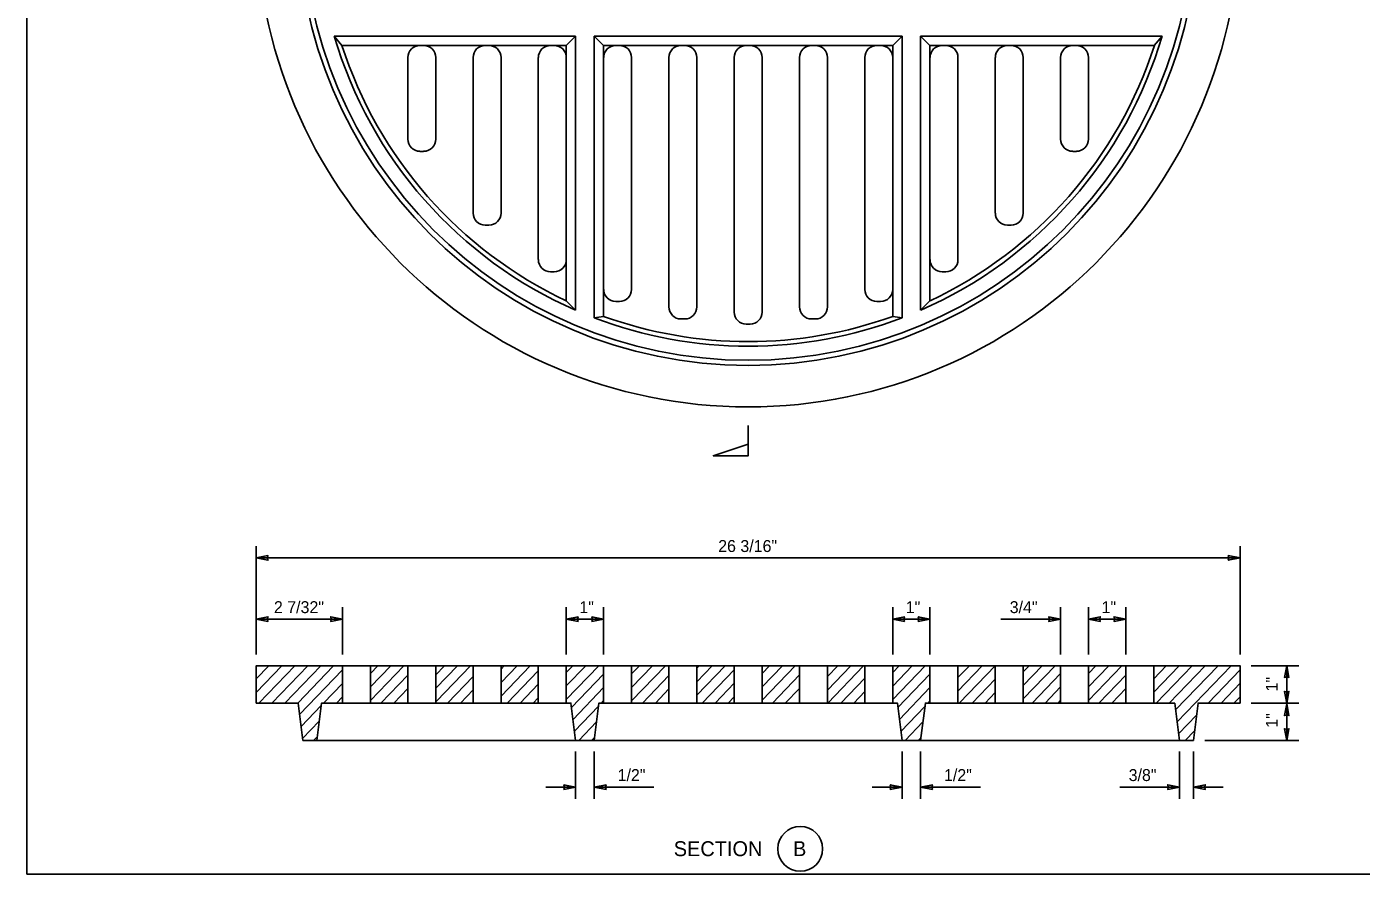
# Model space of a CAD drawing. Extents: x 99862 to 103151, y 100000 to 102076.
# Drawn here: x 99862 to 101651, y 100000 to 101135 of the extents above; entities that cross this region are included whole.
import ezdxf

# ---------------------------------------------------------------- set-up
doc = ezdxf.new("R2010")
doc.units = 0
for name, color, linetype in [('Level 1', 7, 'Continuous'), ('Level 12', 7, 'Continuous'), ('Level 15', 7, 'Continuous'), ('Level 18', 7, 'Continuous'), ('Level 20', 7, 'Continuous'), ('Level 60', 7, 'Continuous'), ('Level 9', 7, 'Continuous')]:
    doc.layers.add(name, color=color, linetype=linetype)

msp = doc.modelspace()

# ---------------------------------------------------------------- linework, layer by layer
at = {"layer": 'Level 1'}
msp.add_lwpolyline([(99862, 99999.5), (103151, 99999.5), (103151, 102075.5), (99862, 102075.5)], close=True, dxfattribs=at)
at = {"layer": 'Level 12'}
for p, q in [((100169.7, 100243.2), (100204, 100278.9)), ((100169.7, 100261.2), (100186.7, 100278.9)), ((100173.3, 100228.9), (100221.4, 100278.9)), ((100190.7, 100228.9), (100238.7, 100278.9)), ((100208, 100228.9), (100256.1, 100278.9)), ((100225.3, 100228.9), (100272.8, 100278.3)), ((100227.9, 100213.5), (100285.3, 100273.3)), ((100322.8, 100250.6), (100350.1, 100278.9)), ((100322.8, 100268.6), (100332.7, 100278.9)), ((100322.8, 100232.5), (100367.4, 100278.9)), ((100409.8, 100266.2), (100422.1, 100278.9)), ((100410.4, 100248.8), (100439.4, 100278.9)), ((100411.1, 100231.4), (100456.7, 100278.9)), ((100497.8, 100256.3), (100519.6, 100278.9)), ((100497.8, 100274.3), (100502.2, 100278.9)), ((100497.8, 100238.2), (100536.9, 100278.9)), ((100506.2, 100228.9), (100547.8, 100272.2)), ((100585.3, 100251.8), (100611.4, 100278.9)), ((100585.3, 100269.8), (100594.1, 100278.9)), ((100585.3, 100233.8), (100628.7, 100278.9)), ((100672.8, 100249.9), (100700.7, 100278.9)), ((100672.8, 100267.9), (100683.4, 100278.9)), ((100672.8, 100231.8), (100718.1, 100278.9)), ((100760.3, 100257.5), (100780.9, 100278.9)), ((100760.3, 100275.5), (100763.6, 100278.9)), ((100760.3, 100239.5), (100798.3, 100278.9)), ((100767.5, 100228.9), (100810.3, 100273.4)), ((100847.8, 100250.7), (100875, 100278.9)), ((100847.8, 100268.7), (100857.6, 100278.9)), ((100847.8, 100232.6), (100892.3, 100278.9)), ((100935.3, 100246.4), (100966.5, 100278.9)), ((100935.3, 100264.5), (100949.2, 100278.9)), ((100935.8, 100228.9), (100983.9, 100278.9)), ((101022.8, 100233.7), (101066.3, 100278.9)), ((101022.8, 100251.7), (101049, 100278.9)), ((101022.8, 100269.7), (101031.6, 100278.9)), ((101110.3, 100245), (101142.9, 100278.9)), ((101110.3, 100263), (101125.6, 100278.9)), ((101112.4, 100229.2), (101160.3, 100279)), ((101197.8, 100252.6), (101223.1, 100278.9)), ((101197.8, 100270.7), (101205.8, 100278.9)), ((101197.8, 100234.6), (101240.4, 100278.9)), ((101285.3, 100250.5), (101312.7, 100278.9)), ((101285.3, 100268.5), (101295.3, 100278.9)), ((101285.3, 100232.4), (101330, 100278.9)), ((101372.8, 100243.4), (101407, 100278.9)), ((101372.8, 100261.4), (101389.6, 100278.9)), ((101376.2, 100228.9), (101424.3, 100278.9)), ((101393.6, 100228.9), (101441.6, 100278.9)), ((101402.1, 100219.7), (101459, 100278.9)), ((101404.1, 100203.8), (101476.3, 100278.9)), ((101445.6, 100228.9), (101488.5, 100273.5)), ((100260, 100228.9), (100285.3, 100255.2)), ((100336.7, 100228.9), (100372.8, 100266.5)), ((100426, 100228.9), (100460.3, 100264.6)), ((100523.5, 100228.9), (100547.8, 100254.2)), ((100592.3, 100223), (100635.3, 100267.7)), ((100687.4, 100228.9), (100722.8, 100265.8)), ((100784.9, 100228.9), (100810.3, 100255.4)), ((100861.6, 100228.9), (100897.8, 100266.6)), ((100953.2, 100228.9), (100985.3, 100262.4)), ((101029.8, 100222.9), (101072.8, 100267.6)), ((101129.5, 100228.9), (101160.3, 100260.9)), ((101209.7, 100228.9), (101247.8, 100268.6)), ((101299.3, 100228.9), (101335.3, 100266.4)), ((101462.9, 100228.9), (101488.5, 100255.4)), ((100277.4, 100228.9), (100285.3, 100237.2)), ((100354, 100228.9), (100372.8, 100248.5)), ((100443.4, 100228.9), (100460.3, 100246.6)), ((100540.9, 100228.9), (100547.8, 100236.1)), ((100594.3, 100207), (100635.3, 100249.7)), ((100704.7, 100228.9), (100722.8, 100247.8)), ((100802.2, 100228.9), (100810.3, 100237.4)), ((100878.9, 100228.9), (100897.8, 100248.6)), ((100970.5, 100228.9), (100985.3, 100244.3)), ((101031.8, 100207), (101072.8, 100249.6)), ((101146.9, 100228.9), (101160.3, 100242.9)), ((101227, 100228.9), (101247.8, 100250.5)), ((101316.6, 100228.9), (101335.3, 100248.4)), ((101480.3, 100228.9), (101488.5, 100237.4)), ((100229.9, 100197.6), (100256.8, 100225.5)), ((100596.3, 100191.1), (100628.6, 100224.6)), ((100632.7, 100228.9), (100635.3, 100231.7)), ((101033.8, 100191), (101066, 100224.5)), ((101070.3, 100228.9), (101072.8, 100231.6)), ((101244.4, 100228.9), (101247.8, 100232.5)), ((100231.9, 100181.6), (100254.2, 100204.8)), ((100602, 100178.9), (100626, 100203.9)), ((101039.5, 100178.9), (101063.4, 100203.8)), ((101406.1, 100187.8), (101429.9, 100212.6)), ((100246.6, 100178.9), (100251.6, 100184.1)), ((100619.3, 100178.9), (100623.4, 100183.1)), ((101056.9, 100178.9), (101060.9, 100183)), ((101414.9, 100178.9), (101427.3, 100191.9))]:
    msp.add_line(p, q, dxfattribs=at)
at = {"layer": 'Level 15'}
for p, q in [((100169.7, 100439.3), (100169.7, 100293.9)), ((101488.5, 100439.3), (101488.5, 100293.9)), ((101488.5, 100423.3), (100169.7, 100423.3)), ((100285.3, 100293.9), (100285.3, 100357.4)), ((100585.3, 100293.9), (100585.3, 100357.4)), ((100635.3, 100293.9), (100635.3, 100357.4)), ((101022.8, 100293.9), (101022.8, 100357.4)), ((101072.8, 100293.9), (101072.8, 100357.4)), ((101247.8, 100293.9), (101247.8, 100357.4)), ((101285.3, 100293.9), (101285.3, 100357.4)), ((101335.3, 100293.9), (101335.3, 100357.4)), ((100285.3, 100341.4), (100169.7, 100341.4)), ((100585.3, 100341.4), (100635.3, 100341.4)), ((101022.8, 100341.4), (101072.8, 100341.4)), ((101167.8, 100341.4), (101247.8, 100341.4)), ((101285.3, 100341.4), (101335.3, 100341.4)), ((101567, 100278.9), (101503.5, 100278.9)), ((101551, 100278.9), (101551, 100228.9)), ((101567, 100228.9), (101503.5, 100228.9)), ((101551, 100227.9), (101551, 100178.9)), ((100597.8, 100163.9), (100597.8, 100100.4)), ((100622.8, 100163.9), (100622.8, 100100.4)), ((101035.3, 100163.9), (101035.3, 100100.4)), ((101060.3, 100163.9), (101060.3, 100100.4)), ((101407.2, 100163.9), (101407.2, 100100.4)), ((101426, 100163.9), (101426, 100100.4)), ((101567, 100178.9), (101441, 100178.9)), ((100597.8, 100116.4), (100557.8, 100116.4)), ((100702.8, 100116.4), (100622.8, 100116.4)), ((101035.3, 100116.4), (100995.3, 100116.4)), ((101140.3, 100116.4), (101060.3, 100116.4)), ((101327.2, 100116.4), (101407.2, 100116.4)), ((101426, 100116.4), (101466, 100116.4))]:
    msp.add_line(p, q, dxfattribs=at)
for points in [[(100169.7, 100423.3), (100185.4, 100420.2), (100184.7, 100423.3), (100185.4, 100426.4)], [(101488.5, 100423.3), (101472.7, 100420.2), (101473.5, 100423.3), (101472.7, 100426.4)], [(100169.7, 100341.4), (100185.4, 100338.3), (100184.7, 100341.4), (100185.4, 100344.5)], [(100285.3, 100341.4), (100269.6, 100338.3), (100270.3, 100341.4), (100269.6, 100344.5)], [(100585.3, 100341.4), (100601.1, 100338.3), (100600.3, 100341.4), (100601.1, 100344.5)], [(100635.3, 100341.4), (100619.6, 100338.3), (100620.3, 100341.4), (100619.6, 100344.5)], [(101022.8, 100341.4), (101038.6, 100338.3), (101037.8, 100341.4), (101038.6, 100344.5)], [(101072.8, 100341.4), (101057.1, 100338.3), (101057.8, 100341.4), (101057.1, 100344.5)], [(101247.8, 100341.4), (101232.1, 100338.3), (101232.8, 100341.4), (101232.1, 100344.5)], [(101285.3, 100341.4), (101301.1, 100338.3), (101300.3, 100341.4), (101301.1, 100344.5)], [(101335.3, 100341.4), (101319.6, 100338.3), (101320.3, 100341.4), (101319.6, 100344.5)], [(101551, 100278.9), (101547.9, 100263.2), (101551, 100263.9), (101554, 100263.2)], [(101551, 100228.9), (101547.9, 100244.6), (101551, 100243.9), (101554, 100244.6)], [(101551, 100227.9), (101547.9, 100212.1), (101551, 100212.9), (101554, 100212.1)], [(101551, 100178.9), (101547.9, 100194.6), (101551, 100193.9), (101554, 100194.6)], [(100597.8, 100116.4), (100582.1, 100113.3), (100582.8, 100116.4), (100582.1, 100119.5)], [(100622.8, 100116.4), (100638.6, 100113.3), (100637.8, 100116.4), (100638.6, 100119.5)], [(101035.3, 100116.4), (101019.6, 100113.3), (101020.3, 100116.4), (101019.6, 100119.5)], [(101060.3, 100116.4), (101076.1, 100113.3), (101075.3, 100116.4), (101076.1, 100119.5)], [(101407.2, 100116.4), (101391.5, 100113.3), (101392.2, 100116.4), (101391.5, 100119.5)], [(101426, 100116.4), (101441.7, 100113.3), (101441, 100116.4), (101441.7, 100119.5)]]:
    msp.add_lwpolyline(points, close=True, dxfattribs=at)
at = {"layer": 'Level 18'}
for p, q in [((100274.3, 101122.6), (100597.8, 101122.6)), ((100284.6, 101110.1), (100274.3, 101122.6)), ((100585.3, 101110.1), (100597.8, 101122.6)), ((100597.8, 100755.2), (100597.8, 101122.6)), ((100622.8, 100745), (100622.8, 101122.6)), ((100635.3, 101110.1), (100622.8, 101122.6)), ((100622.8, 101122.6), (101035.3, 101122.6)), ((101022.8, 101110.1), (101035.3, 101122.6)), ((101035.3, 100745), (101035.3, 101122.6)), ((101060.3, 100755.2), (101060.3, 101122.6)), ((101060.3, 101122.6), (101383.9, 101122.6)), ((101060.3, 101122.6), (101072.8, 101110.1)), ((101373.5, 101110.1), (101383.9, 101122.6)), ((100284.6, 101110.1), (100585.3, 101110.1)), ((100389.1, 101110.1), (100394.1, 101110.1)), ((100476.6, 101110.1), (100481.6, 101110.1)), ((100564.1, 101110.1), (100569.1, 101110.1)), ((100585.3, 100767.8), (100585.3, 101110.1)), ((100635.3, 100747), (100635.3, 101110.1)), ((100635.3, 101110.1), (101022.8, 101110.1)), ((100651.6, 101110.1), (100656.6, 101110.1)), ((100739.1, 101110.1), (100744.1, 101110.1)), ((100826.6, 101110.1), (100831.6, 101110.1)), ((100914.1, 101110.1), (100919.1, 101110.1)), ((101001.6, 101110.1), (101006.6, 101110.1)), ((101022.8, 100747), (101022.8, 101110.1)), ((101072.8, 101110.1), (101373.5, 101110.1)), ((101072.8, 100767.8), (101072.8, 101110.1)), ((101089.1, 101110.1), (101094.1, 101110.1)), ((101176.6, 101110.1), (101181.6, 101110.1)), ((101264.1, 101110.1), (101269.1, 101110.1)), ((100372.8, 100984.4), (100372.8, 101093.8)), ((100410.3, 100984.4), (100410.3, 101093.8)), ((100460.3, 100885.4), (100460.3, 101093.8)), ((100497.8, 100885.4), (100497.8, 101093.8)), ((100547.8, 100823), (100547.8, 101093.8)), ((100585.3, 100823), (100585.3, 101093.8)), ((100635.3, 100783.2), (100635.3, 101093.8)), ((100672.8, 100783.2), (100672.8, 101093.8)), ((100722.8, 100759.7), (100722.8, 101093.8)), ((100760.3, 100759.7), (100760.3, 101093.8)), ((100810.3, 100752.8), (100810.3, 101093.8)), ((100847.8, 100752.8), (100847.8, 101093.8)), ((100897.8, 100759.7), (100897.8, 101093.8)), ((100935.3, 100759.7), (100935.3, 101093.8)), ((100985.3, 100783.2), (100985.3, 101093.8)), ((101022.8, 100783.2), (101022.8, 101093.8)), ((101072.8, 100823), (101072.8, 101093.8)), ((101110.3, 100823), (101110.3, 101093.8)), ((101160.3, 100885.4), (101160.3, 101093.8)), ((101197.8, 100885.4), (101197.8, 101093.8)), ((101247.8, 100984.4), (101247.8, 101093.8)), ((101285.3, 100984.4), (101285.3, 101093.8)), ((100389.1, 100968.1), (100394.1, 100968.1)), ((101269.1, 100968.1), (101264.1, 100968.1)), ((100476.6, 100869.1), (100481.6, 100869.1)), ((101181.6, 100869.1), (101176.6, 100869.1)), ((100564.1, 100806.7), (100569.1, 100806.7)), ((101094.1, 100806.7), (101089.1, 100806.7)), ((100585.3, 100767.8), (100597.8, 100755.2)), ((100651.6, 100766.9), (100656.6, 100766.9)), ((101006.6, 100766.9), (101001.6, 100766.9)), ((101072.8, 100767.8), (101060.3, 100755.2)), ((100635.3, 100747), (100622.8, 100745)), ((100739.1, 100743.5), (100744.1, 100743.5)), ((100826.6, 100736.6), (100831.6, 100736.6)), ((100919.1, 100743.5), (100914.1, 100743.5)), ((101022.8, 100747), (101035.3, 100745)), ((100285.3, 100278.9), (101372.8, 100278.9)), ((100285.3, 100228.9), (100585.3, 100228.9)), ((100635.3, 100228.9), (101022.8, 100228.9)), ((101072.8, 100228.9), (101372.8, 100228.9)), ((100251, 100178.9), (101407.2, 100178.9))]:
    msp.add_line(p, q, dxfattribs=at)
for points in [[(100285.3, 100228.9), (100285.3, 100278.9), (100169.7, 100278.9), (100169.7, 100228.9), (100226, 100228.9), (100232.2, 100178.9), (100251, 100178.9), (100257.2, 100228.9), (100285.3, 100228.9)], [(100372.8, 100228.9), (100372.8, 100278.9), (100322.8, 100278.9), (100322.8, 100228.9), (100372.8, 100228.9)], [(100460.3, 100228.9), (100460.3, 100278.9), (100410.3, 100278.9), (100410.3, 100228.9), (100460.3, 100228.9)], [(100547.8, 100228.9), (100547.8, 100278.9), (100497.8, 100278.9), (100497.8, 100228.9), (100547.8, 100228.9)], [(100635.3, 100228.9), (100635.3, 100278.9), (100585.3, 100278.9), (100585.3, 100228.9), (100591.6, 100228.9), (100597.8, 100178.9), (100622.8, 100178.9), (100629.1, 100228.9), (100635.3, 100228.9)], [(100694.9, 100278.9), (100672.8, 100278.9), (100672.8, 100228.9), (100722.8, 100228.9), (100722.8, 100278.9), (100694.9, 100278.9)], [(100810.3, 100228.9), (100810.3, 100278.9), (100760.3, 100278.9), (100760.3, 100228.9), (100810.3, 100228.9)], [(100872.2, 100278.9), (100847.8, 100278.9), (100847.8, 100228.9), (100897.8, 100228.9), (100897.8, 100278.9), (100872.2, 100278.9)], [(100985.3, 100228.9), (100985.3, 100278.9), (100935.3, 100278.9), (100935.3, 100228.9), (100985.3, 100228.9)], [(101072.8, 100228.9), (101072.8, 100278.9), (101022.8, 100278.9), (101022.8, 100228.9), (101029.1, 100228.9), (101035.3, 100178.9), (101060.3, 100178.9), (101066.6, 100228.9), (101072.8, 100228.9)], [(101160.3, 100228.9), (101160.3, 100278.9), (101110.3, 100278.9), (101110.3, 100228.9), (101160.3, 100228.9)], [(101247.8, 100228.9), (101247.8, 100278.9), (101197.8, 100278.9), (101197.8, 100228.9), (101247.8, 100228.9)], [(101335.3, 100228.9), (101335.3, 100278.9), (101285.3, 100278.9), (101285.3, 100228.9), (101335.3, 100228.9)], [(101401, 100228.9), (101407.2, 100178.9), (101426, 100178.9), (101432.2, 100228.9), (101488.5, 100228.9), (101488.5, 100278.9), (101372.8, 100278.9), (101372.8, 100228.9), (101401, 100228.9)]]:
    msp.add_lwpolyline(points, dxfattribs=at)
for radius in [659.4, 603.8, 596.9]:
    msp.add_circle((100829.1, 101285.1), radius, dxfattribs=at)
for centre, radius, start, end in [((100829.1, 101285.1), 578.1, 196.3247, 246.4218), ((100829.1, 101285.1), 578.1, 293.5782, 343.6753), ((100829.1, 101285.1), 571.9, 197.819, 244.7715), ((100389.1, 101093.8), 16.2, 90, 180), ((100394.1, 101093.8), 16.2, 0, 90), ((100476.6, 101093.8), 16.2, 90, 180), ((100481.6, 101093.8), 16.2, 0, 90), ((100564.1, 101093.8), 16.2, 90, 180), ((100569.1, 101093.8), 16.2, 0, 90), ((100651.6, 101093.8), 16.2, 90, 180), ((100656.6, 101093.8), 16.2, 0, 90), ((100739.1, 101093.8), 16.2, 90, 180), ((100744.1, 101093.8), 16.2, 0, 90), ((100826.6, 101093.8), 16.2, 90, 180), ((100831.6, 101093.8), 16.2, 0, 90), ((100914.1, 101093.8), 16.2, 90, 180), ((100919.1, 101093.8), 16.2, 0, 90), ((101001.6, 101093.8), 16.2, 90, 180), ((101006.6, 101093.8), 16.2, 0, 90), ((101089.1, 101093.8), 16.2, 90, 180), ((100829.1, 101285.1), 571.9, 295.2285, 342.181), ((101094.1, 101093.8), 16.2, 0, 90), ((101176.6, 101093.8), 16.2, 90, 180), ((101181.6, 101093.8), 16.2, 0, 90), ((101264.1, 101093.8), 16.2, 90, 180), ((101269.1, 101093.8), 16.2, 0, 90), ((100389.1, 100984.4), 16.2, 180, 270), ((100394.1, 100984.4), 16.2, 270, 0), ((101264.1, 100984.4), 16.2, 180, 270), ((101269.1, 100984.4), 16.2, 270, 0), ((100476.6, 100885.4), 16.2, 180, 270), ((100481.6, 100885.4), 16.2, 270, 0), ((101176.6, 100885.4), 16.2, 180, 270), ((101181.6, 100885.4), 16.2, 270, 0), ((100564.1, 100823), 16.2, 180, 270), ((100569.1, 100823), 16.2, 270, 0), ((101089.1, 100823), 16.2, 180, 270), ((101094.1, 100823), 16.2, 270, 0), ((100651.6, 100783.2), 16.2, 180, 270), ((100656.6, 100783.2), 16.2, 270, 0), ((101001.6, 100783.2), 16.2, 180, 270), ((101006.6, 100783.2), 16.2, 270, 0), ((100739.1, 100759.7), 16.2, 180, 270), ((100744.1, 100759.7), 16.2, 270, 0), ((100914.1, 100759.7), 16.2, 180, 270), ((100919.1, 100759.7), 16.2, 270, 0), ((100829.1, 101285.1), 578.1, 249.0988, 290.9012), ((100829.1, 101285.1), 571.9, 250.1964, 289.8036), ((100826.6, 100752.8), 16.2, 180, 270), ((100831.6, 100752.8), 16.2, 270, 0.0005)]:
    msp.add_arc(centre, radius, start, end, dxfattribs=at)
at = {"layer": 'Level 60'}
msp.add_line((99862, 99999.5), (99862, 99999.5), dxfattribs=at)
at = {"layer": 'Level 9'}
msp.add_line((100829.1, 100600.7), (100829.1, 100560.2), dxfattribs=at)
msp.add_lwpolyline([(100829.1, 100575.7), (100782.2, 100560.2), (100829.1, 100560.2)], close=True, dxfattribs=at)
msp.add_circle((100898.9, 100033.6), 30, dxfattribs=at)

# ---------------------------------------------------------------- texts
at = {"layer": 'Level 20'}
for s, rotation, p in [('26 3/16"', 0, (100788.9, 100431.3)), ('2 7/32"', 0, (100193.4, 100349.4)), ('1"', 0, (100602.8, 100349.4)), ('1"', 0, (101040.3, 100349.4)), ('3/4"', 360, (101179.7, 100349.4)), ('1"', 0, (101302.8, 100349.4)), ('1"', 90, (101539, 100244.5)), ('1"', 90, (101539, 100195.9)), ('3/8"', 360, (101339.1, 100124.4))]:
    msp.add_text(s, height=16, rotation=rotation, dxfattribs=at).set_placement(p)
for s, height, p in [('1/2"', 16, (100654.1, 100124.4)), ('1/2"', 16, (101091.6, 100124.4)), ('SECTION', 20, (100729.3, 100023.8)), ('B', 20, (100889.2, 100023.8))]:
    msp.add_text(s, height=height, dxfattribs=at).set_placement(p)

doc.saveas('drawing.dxf')
